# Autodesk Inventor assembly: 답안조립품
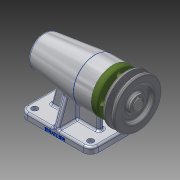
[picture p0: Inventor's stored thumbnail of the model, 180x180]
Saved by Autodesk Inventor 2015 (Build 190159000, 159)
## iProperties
Created: 2018-09
Part Number: 답안조립품
Document SubType Name: Assembly
Designer: pc
Author: pc
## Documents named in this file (12)
- C:\Users\pc\Desktop\480907V1016\답안조립품.iam
- C:\Users\pc\Desktop\480907V1016\본체.ipt
- C:\Users\pc\Desktop\480907V1016\V벨트풀리.ipt
- C:\Users\pc\Desktop\480907V1016\멈춤나사 M3.ipt
- C:\Users\pc\Desktop\480907V1016\베어링 6004.ipt
- C:\Users\pc\Desktop\480907V1016\베어링 51202.ipt
- C:\Users\pc\Desktop\480907V1016\볼트 M4.ipt
- C:\Users\pc\Desktop\480907V1016\어댑터슬리브.ipt
- C:\Users\pc\Desktop\480907V1016\오일 실.ipt
- C:\Users\pc\Desktop\480907V1016\축.ipt
- C:\Users\pc\Desktop\480907V1016\커버.ipt
- C:\Users\pc\Desktop\480907V1016\키 5 x 5 x 16.ipt
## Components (1 placed, 1 different names)
1. V벨트풀리:1 — 각도:2
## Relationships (1: Angle 1)
- 각도:2 [Angle]: V벨트풀리:1
